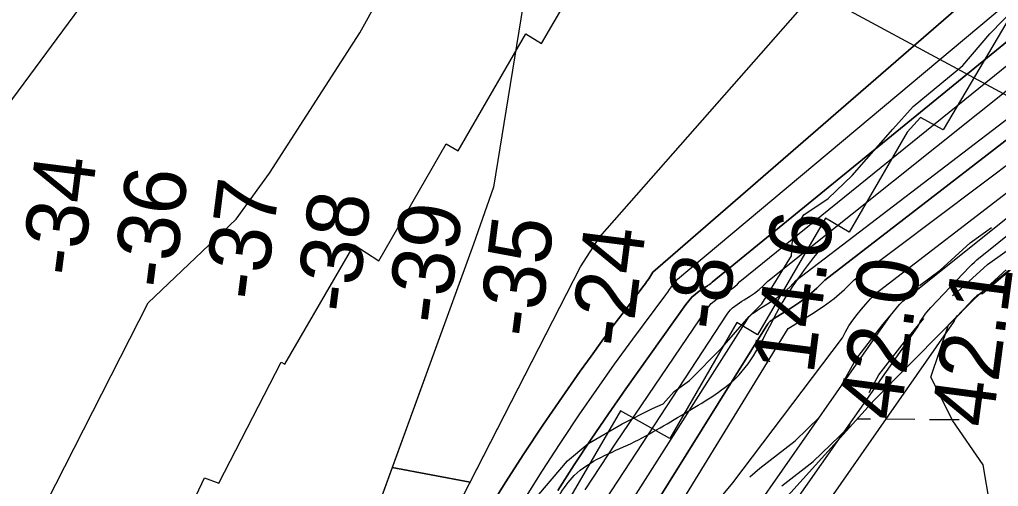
# Model space of a CAD drawing. Extents: x 3271442 to 3309282, y 752266 to 777610.
# Drawn here: x 3288016 to 3289076, y 761598 to 762104 of the extents above; entities that cross this region are included whole.
import ezdxf

# ---------------------------------------------------------------- set-up
doc = ezdxf.new("R2010")
doc.units = 0
for name, color, linetype in [('V-RIVR-EDGE', 7, 'Continuous'), ('V-RIVR-RANG', 7, 'Continuous'), ('V-ROAD-CNTR', 7, 'Continuous'), ('V-RRAP-FSHR', 7, 'Continuous'), ('V-RRAP-RVMT', 7, 'Continuous'), ('V-SITE-VEGE', 7, 'Continuous'), ('V-TOPO-DPTH', 7, 'Continuous'), ('V-TOPO-MAJR', 7, 'Continuous'), ('V-TOPO-MINR', 7, 'Continuous'), ('V-TOPO-WATR', 7, 'Continuous'), ('V-WETL-SWMP', 7, 'Continuous')]:
    doc.layers.add(name, color=color, linetype=linetype)

msp = doc.modelspace()

# ---------------------------------------------------------------- linework, layer by layer
at = {"layer": 'V-RIVR-EDGE'}
msp.add_lwpolyline([(3288561.9, 761569.6), (3288609.4, 761625.5), (3288631.6, 761644.2), (3288668.6, 761665.8), (3288701.7, 761682.2), (3288713, 761687.4), (3288725.2, 761700.9), (3288741.8, 761712.6), (3288776.7, 761748.1), (3288806.3, 761781.9), (3288820.2, 761795.8), (3288852.1, 761847.9), (3288853.4, 761864.9), (3288853.9, 761874), (3288865.7, 761892.2), (3288891.8, 761910), (3288917.9, 761934.7), (3288962, 761985), (3288984.2, 762009.7), (3289037.8, 762053.9), (3289067, 762088.2), (3289096.6, 762118.1)], dxfattribs=at)
at = {"layer": 'V-RIVR-RANG'}
msp.add_line((3289422.7, 761839.3), (3288525.2, 762323.9), dxfattribs=at)
at = {"layer": 'V-ROAD-CNTR'}
for points in [[(3288991.1, 761815.7), (3289013.3, 761832.3), (3289045.7, 761861.9), (3289068.9, 761878.3)], [(3289026.7, 761804.8), (3289032.4, 761809.1), (3289064.6, 761838.5), (3289104.8, 761867)], [(3288905.5, 761706.1), (3288921.8, 761735.3), (3288951.2, 761773.3), (3288963.1, 761787.5)], [(3288936.3, 761699.6), (3288946.9, 761718.7), (3288974.6, 761754.5), (3288995.7, 761779.8)], [(3288807, 761608.5), (3288817.8, 761617.6), (3288856, 761647.5), (3288882.8, 761673.5)], [(3288841.9, 761598.4), (3288875.7, 761624.8), (3288913.5, 761661.4), (3288915.9, 761665.3)]]:
    msp.add_lwpolyline(points, dxfattribs=at)
at = {"layer": 'V-RRAP-FSHR'}
msp.add_spline([(3288024.6, 760324), (3288039.3, 760373.1), (3288065.4, 760447.4), (3288088.5, 760530), (3288126.8, 760603.6), (3288137.9, 760646.8), (3288151, 760667.9), (3288170.6, 760680.2), (3288214.9, 760704), (3288256.5, 760693.3), (3288288, 760697.9), (3288339, 760715), (3288380, 760710.8), (3288399.4, 760726.3), (3288427.1, 760792.6), (3288462, 760862.2), (3288467.4, 760912.7), (3288487.8, 760995.5), (3288477.6, 761071), (3288451.3, 761142.3), (3288448.8, 761210.4), (3288443.2, 761290.4), (3288453.5, 761341), (3288469, 761381.1), (3288509, 761459.8), (3288586.4, 761563.5), (3288616.8, 761609.7), (3288678.4, 761644.6), (3288740.1, 761679.4), (3288795.5, 761719), (3288838.6, 761790.4), (3288890.2, 761863.5)], degree=3, dxfattribs=at)
at = {"layer": 'V-RRAP-RVMT'}
for points in [[(3288047.9, 761168.8), (3288047.6, 761183.6), (3288050, 761184.2), (3288052.9, 761205), (3288029.6, 761220.6), (3288061.8, 761268.1), (3288071.1, 761334.6), (3288077.4, 761334.7), (3288114, 761483.6), (3288153.2, 761474.1), (3288216.1, 761607.4), (3288231.7, 761601.6), (3288299, 761732.4), (3288303.1, 761730.4), (3288378.1, 761859.6), (3288404.9, 761842.3), (3288478, 761969), (3288490.9, 761961.4), (3288564.4, 762088.4), (3288581.3, 762077.7), (3288654.8, 762204)], [(3289090.3, 762108.9), (3289016.5, 761984.2), (3288991.9, 761997.7), (3288977.5, 761981.7), (3288914.6, 761873.4), (3288889, 761888.6), (3288815.3, 761762.2), (3288793, 761775.5), (3288720.4, 761650), (3288666.7, 761679.7), (3288593.8, 761554.4), (3288571.6, 761568.1), (3288510.1, 761451), (3288498.7, 761456.4), (3288469.1, 761394.2), (3288473.9, 761394), (3288445.6, 761283), (3288456.3, 761281.9), (3288446.5, 761214.5), (3288447, 761190.5), (3288462.2, 761191.4), (3288462.5, 761177.3)]]:
    msp.add_lwpolyline(points, dxfattribs=at)
at = {"layer": 'V-SITE-VEGE'}
msp.add_lwpolyline([(3289117, 761109.9), (3289055.4, 761114.6), (3289027, 761185.7), (3289027, 761200.1), (3289027, 761365.7), (3289017.5, 761379.9), (3289012.8, 761436.8), (3289017.5, 761469.9), (3289074.3, 761522), (3289074.3, 761536.2), (3289060.1, 761621.5), (3289027, 761668.9), (3289003.3, 761716.3), (3289022.3, 761773.1), (3289045.9, 761796.8), (3289107.5, 761853.6)], dxfattribs=at)
at = {"layer": 'V-TOPO-DPTH'}
for p, q in [((3289452.3, 762256.7), (3288888.2, 761821.3)), ((3288888.2, 761821.3), (3288879.7, 761812.8)), ((3288879.7, 761812.8), (3288870.8, 761804.8)), ((3288861.3, 761797.6), (3288851.4, 761790.9)), ((3288870.8, 761804.8), (3288861.3, 761797.6)), ((3288851.4, 761790.9), (3288832.6, 761779.4)), ((3288827.8, 761775.7), (3288827.1, 761774.9)), ((3288828.5, 761776.4), (3288827.8, 761775.7)), ((3288829.2, 761777), (3288828.5, 761776.4)), ((3288830.1, 761777.6), (3288829.2, 761777)), ((3288830.9, 761778.2), (3288830.1, 761777.6)), ((3288831.7, 761778.8), (3288830.9, 761778.2)), ((3288832.6, 761779.4), (3288831.7, 761778.8)), ((3288826.5, 761774.1), (3288629.6, 761458.5)), ((3288827.1, 761774.9), (3288826.5, 761774.1))]:
    msp.add_line(p, q, dxfattribs=at)
for points in [[(3288503.8, 761602.5), (3288623.5, 761835.8), (3288633.9, 761852), (3288644.3, 761868.2), (3289076.3, 762359.1), (3289585.9, 762757.5), (3289883.5, 763118.2)], [(3288320.8, 762441.7), (3287923.6, 761904.9)], [(3288320.8, 762441.7), (3287923.6, 761904.9)], [(3287738.3, 760513), (3288157.4, 760980.6), (3288277.3, 761160.7), (3288623.5, 761835.8), (3288633.9, 761852), (3288644.3, 761868.2), (3289076.3, 762359.1)], [(3289231.7, 762289.3), (3288702, 761830.1), (3288700.8, 761828.3), (3288699.7, 761826.5), (3288698.6, 761824.7), (3288697.4, 761823), (3288696.3, 761821.2), (3288695.1, 761819.5), (3288693.8, 761817.8), (3288692.6, 761816.1), (3288670.7, 761787.6), (3288658.6, 761771.5), (3288646.7, 761755.4), (3288634.9, 761739.1), (3288623.3, 761722.8), (3288603.6, 761694.8), (3288582.6, 761664.2), (3288562, 761633.3), (3288542, 761602), (3288522.5, 761570.3)], [(3289231.7, 762289.3), (3288702, 761830.1), (3288700.8, 761828.3), (3288699.7, 761826.5), (3288698.6, 761824.7), (3288697.4, 761823), (3288696.3, 761821.2), (3288695.1, 761819.5), (3288693.8, 761817.8), (3288692.6, 761816.1), (3288670.7, 761787.6), (3288658.6, 761771.5), (3288646.7, 761755.4), (3288634.9, 761739.1), (3288623.3, 761722.8), (3288603.6, 761694.8), (3288582.6, 761664.2), (3288562, 761633.3), (3288542, 761602), (3288522.5, 761570.3)], [(3288651.1, 761583.8), (3288782.4, 761784.4), (3288784.2, 761786.9), (3288786.2, 761789.2), (3288788.4, 761791.3), (3288790.8, 761793.3), (3288793.3, 761795.1), (3288795.8, 761796.8), (3288798.4, 761798.5), (3288801, 761800.2), (3288806.8, 761803.8), (3288812.1, 761807.4), (3288817.2, 761811.4), (3288821.9, 761815.7), (3288826.4, 761820.4), (3289419.8, 762294)], [(3288651.1, 761583.8), (3288782.4, 761784.4), (3288784.2, 761786.9), (3288786.2, 761789.2), (3288788.4, 761791.3), (3288790.8, 761793.3), (3288793.3, 761795.1), (3288795.8, 761796.8), (3288798.4, 761798.5), (3288801, 761800.2), (3288806.8, 761803.8), (3288812.1, 761807.4), (3288817.2, 761811.4), (3288821.9, 761815.7), (3288826.4, 761820.4), (3289419.8, 762294)], [(3288598.8, 761593.6), (3288616.7, 761621.5), (3288635, 761649.2), (3288653.7, 761676.6), (3288672.7, 761703.8), (3288737.5, 761794.9), (3288740.8, 761799), (3288744.3, 761802.8), (3288748.2, 761806.2), (3288752.3, 761809.4), (3288759.3, 761814.1), (3288760.2, 761814.7), (3288761.1, 761815.3), (3288762, 761815.9), (3288762.9, 761816.5), (3288763.8, 761817.1), (3288764.6, 761817.7), (3288765.4, 761818.4), (3288766.2, 761819.2), (3289335.6, 762283.8)], [(3289335.6, 762283.8), (3288766.2, 761819.2), (3288765.4, 761818.4), (3288764.6, 761817.7), (3288763.8, 761817.1), (3288762.9, 761816.5), (3288762, 761815.9), (3288761.1, 761815.3), (3288760.2, 761814.7), (3288759.3, 761814.1), (3288752.3, 761809.4), (3288748.2, 761806.2), (3288744.3, 761802.8), (3288740.8, 761799), (3288737.5, 761794.9), (3288672.7, 761703.8), (3288653.7, 761676.6), (3288635, 761649.2), (3288616.7, 761621.5), (3288598.8, 761593.6)], [(3287924.8, 761194.9), (3288044.8, 761580.5), (3288155, 761797), (3288250.5, 761887.3), (3288286.3, 761937.2), (3288384.4, 762089.4), (3288463.3, 762232.2), (3288501.5, 762258.3), (3288522.9, 762258.2), (3288549.1, 762248.6), (3288563.3, 762217.6), (3288568, 762160.5), (3288529.3, 761922.3), (3288507.7, 761860.5), (3288419.5, 761618.5), (3288503.8, 761602.5)], [(3288549.1, 762248.6), (3288563.3, 762217.6), (3288568, 762160.5), (3288529.3, 761922.3), (3288507.7, 761860.5), (3288251, 761156), (3288215.2, 761127.5), (3288165.2, 761115.7), (3288112.8, 761113.5), (3288048.5, 761116), (3287998.5, 761125.7), (3287955.6, 761132.9), (3287934.2, 761152), (3287924.8, 761194.9), (3288044.8, 761580.5), (3288155, 761797), (3288250.5, 761887.3), (3288286.3, 761937.2), (3288384.4, 762089.4), (3288463.3, 762232.2), (3288501.5, 762258.3), (3288522.9, 762258.2), (3288549.1, 762248.6)], [(3288501.3, 761597.5), (3288503.8, 761602.5), (3288419.5, 761618.5), (3288416.6, 761610.4), (3288251, 761156), (3288215.2, 761127.5), (3288165.2, 761115.7), (3288112.8, 761113.5), (3288048.5, 761116), (3287998.5, 761125.7)]]:
    msp.add_lwpolyline(points, dxfattribs=at)
at = {"layer": 'V-TOPO-MAJR'}
for p, q in [((3288972.9, 761798.8), (3289527.9, 762241.9)), ((3288969.4, 761795), (3288972.9, 761798.8)), ((3288959.4, 761783), (3288962.7, 761787.1)), ((3288962.7, 761787.1), (3288966, 761791.1)), ((3288966, 761791.1), (3288969.4, 761795)), ((3288699, 761410.1), (3288959.4, 761783))]:
    msp.add_line(p, q, dxfattribs=at)
at = {"layer": 'V-TOPO-MINR'}
for p, q in [((3289059.1, 761807.1), (3289603.7, 762270.1)), ((3288888.2, 761821.3), (3289452.3, 762256.7)), ((3289053.2, 761843.5), (3289565.9, 762256)), ((3288857, 761820.9), (3289416.7, 762249.1)), ((3288920.2, 761821.6), (3289462.9, 762231)), ((3288943, 761806.5), (3289489.6, 762228)), ((3289047.7, 761838.4), (3289050.4, 761841)), ((3289050.4, 761841), (3289053.2, 761843.5)), ((3289003.2, 761791.6), (3289045.1, 761835.7)), ((3289045.1, 761835.7), (3289047.7, 761838.4)), ((3288850.6, 761814.3), (3288857, 761820.9)), ((3288879.7, 761812.8), (3288888.2, 761821.3)), ((3288909.5, 761811.2), (3288920.2, 761821.6)), ((3288836.6, 761802.6), (3288843.8, 761808.1)), ((3288843.8, 761808.1), (3288850.6, 761814.3)), ((3288870.8, 761804.8), (3288879.7, 761812.8)), ((3288898.4, 761801.5), (3288909.5, 761811.2)), ((3288816.8, 761789.8), (3288829, 761797.4)), ((3288829, 761797.4), (3288836.6, 761802.6)), ((3288851.4, 761790.9), (3288861.3, 761797.6)), ((3288861.3, 761797.6), (3288870.8, 761804.8)), ((3288886.5, 761792.7), (3288898.4, 761801.5)), ((3288932.9, 761795.4), (3288937.9, 761801)), ((3288937.9, 761801), (3288943, 761806.5)), ((3289033.5, 761784.3), (3289049.2, 761800.9)), ((3289049.2, 761800.9), (3289050.2, 761801.9)), ((3289050.2, 761801.9), (3289051.2, 761802.9)), ((3289051.2, 761802.9), (3289052.2, 761803.8)), ((3289052.2, 761803.8), (3289053.3, 761804.8)), ((3289053.3, 761804.8), (3289053.5, 761805)), ((3289053.5, 761805), (3289054.5, 761805.7)), ((3289054.5, 761805.7), (3289055.6, 761806.3)), ((3289055.6, 761806.3), (3289056.7, 761806.7)), ((3289056.7, 761806.7), (3289057.9, 761807)), ((3289057.9, 761807), (3289059.1, 761807.1)), ((3288810, 761785.1), (3288811.7, 761786.4)), ((3288811.7, 761786.4), (3288813.3, 761787.5)), ((3288813.3, 761787.5), (3288815, 761788.7)), ((3288815, 761788.7), (3288816.8, 761789.8)), ((3288832.6, 761779.4), (3288851.4, 761790.9)), ((3288874, 761784.4), (3288886.5, 761792.7)), ((3288923.2, 761784.1), (3288928, 761789.8)), ((3288928, 761789.8), (3288932.9, 761795.4)), ((3288997, 761784.4), (3288999, 761786.8)), ((3288999, 761786.8), (3289001, 761789.2)), ((3289001, 761789.2), (3289003.2, 761791.6)), ((3288589.8, 761148.3), (3289028.4, 761776.6)), ((3288640.3, 761521.6), (3288804.5, 761779.2)), ((3288804.5, 761779.2), (3288805.7, 761780.9)), ((3288805.7, 761780.9), (3288807, 761782.4)), ((3288807, 761782.4), (3288808.5, 761783.8)), ((3288808.5, 761783.8), (3288810, 761785.1)), ((3288827.1, 761774.9), (3288827.8, 761775.7)), ((3288827.8, 761775.7), (3288828.5, 761776.4)), ((3288828.5, 761776.4), (3288829.2, 761777)), ((3288829.2, 761777), (3288830.1, 761777.6)), ((3288830.1, 761777.6), (3288830.9, 761778.2)), ((3288830.9, 761778.2), (3288831.7, 761778.8)), ((3288831.7, 761778.8), (3288832.6, 761779.4)), ((3288848.5, 761768.9), (3288874, 761784.4)), ((3288914.5, 761772), (3288918.6, 761778.1)), ((3288918.6, 761778.1), (3288923.2, 761784.1)), ((3288990.5, 761773.7), (3288991.8, 761776.5)), ((3288991.8, 761776.5), (3288993.3, 761779.2)), ((3288993.3, 761779.2), (3288995.1, 761781.8)), ((3288995.1, 761781.8), (3288997, 761784.4)), ((3289028.4, 761776.6), (3289028.8, 761777.7)), ((3289028.8, 761777.7), (3289029.3, 761778.7)), ((3289029.3, 761778.7), (3289029.8, 761779.7)), ((3289029.8, 761779.7), (3289030.5, 761780.7)), ((3289030.5, 761780.7), (3289031.2, 761781.7)), ((3289031.2, 761781.7), (3289031.9, 761782.6)), ((3289031.9, 761782.6), (3289032.7, 761783.5)), ((3289032.7, 761783.5), (3289033.5, 761784.3)), ((3288609, 761230.8), (3288989.3, 761770.7)), ((3288618.8, 761394.8), (3288848.5, 761768.9)), ((3288629.6, 761458.5), (3288826.5, 761774.1)), ((3288826.5, 761774.1), (3288827.1, 761774.9)), ((3288907.4, 761758.9), (3288910.8, 761765.5)), ((3288910.8, 761765.5), (3288914.5, 761772)), ((3288989.3, 761770.7), (3288990.5, 761773.7)), ((3288788.7, 761601.9), (3288907.4, 761758.9)), ((3288778.2, 761589.3), (3288788.7, 761601.9))]:
    msp.add_line(p, q, dxfattribs=at)
for points in [[(3288320.8, 762441.7), (3287923.6, 761904.9)], [(3287738.3, 760513), (3288157.4, 760980.6), (3288277.3, 761160.7), (3288623.5, 761835.8), (3288633.9, 761852), (3288644.3, 761868.2), (3289076.3, 762359.1)], [(3288628.5, 761594.3), (3288645.1, 761619.6), (3288661.9, 761644.8), (3288760.1, 761789.6), (3288762.6, 761792.9), (3288765.3, 761796), (3288768.3, 761798.8), (3288771.6, 761801.3), (3288772.2, 761801.8), (3288775.3, 761803.9), (3288778.4, 761806.1), (3288781.6, 761808.1), (3288784.8, 761810.1), (3288787.9, 761812.3), (3288790.8, 761814.6), (3288793.5, 761817.1), (3288796.1, 761819.9), (3289388, 762298.8)], [(3288522.5, 761570.3), (3288542, 761602), (3288562, 761633.3), (3288582.6, 761664.2), (3288603.6, 761694.8), (3288623.3, 761722.8), (3288634.9, 761739.1), (3288646.7, 761755.4), (3288658.6, 761771.5), (3288670.7, 761787.6), (3288692.6, 761816.1), (3288693.8, 761817.8), (3288695.1, 761819.5), (3288696.3, 761821.2), (3288697.4, 761823), (3288698.6, 761824.7), (3288699.7, 761826.5), (3288700.8, 761828.3), (3288702, 761830.1), (3289231.7, 762289.3)], [(3288598.8, 761593.6), (3288616.7, 761621.5), (3288635, 761649.2), (3288653.7, 761676.6), (3288672.7, 761703.8), (3288737.5, 761794.9), (3288740.8, 761799), (3288744.3, 761802.8), (3288748.2, 761806.2), (3288752.3, 761809.4), (3288759.3, 761814.1), (3288760.2, 761814.7), (3288761.1, 761815.3), (3288762, 761815.9), (3288762.9, 761816.5), (3288763.8, 761817.1), (3288764.6, 761817.7), (3288765.4, 761818.4), (3288766.2, 761819.2), (3289335.6, 762283.8)], [(3288033, 760667), (3288311.4, 761122.9), (3288527.5, 761523.3), (3288545.2, 761554), (3288563.3, 761584.5), (3288582, 761614.6), (3288601.3, 761644.4), (3288603.5, 761647.7), (3288622.1, 761675.5), (3288641.1, 761703.1), (3288660.5, 761730.3), (3288680.3, 761757.4), (3288715.9, 761805.6), (3288718, 761808.4), (3288720.1, 761811.2), (3288722.2, 761814), (3288724.4, 761816.9), (3288726.5, 761819.7), (3288728.6, 761822.5), (3289235.3, 762246.9)]]:
    msp.add_lwpolyline(points, dxfattribs=at)
msp.add_lwpolyline([(3287924.8, 761194.9), (3288044.8, 761580.5), (3288155, 761797), (3288250.5, 761887.3), (3288286.3, 761937.2), (3288384.4, 762089.4), (3288463.3, 762232.2), (3288501.5, 762258.3), (3288522.9, 762258.2), (3288549.1, 762248.6), (3288563.3, 762217.6), (3288568, 762160.5), (3288529.3, 761922.3), (3288507.7, 761860.5), (3288251, 761156), (3288215.2, 761127.5), (3288165.2, 761115.7), (3288112.8, 761113.5), (3288048.5, 761116), (3287998.5, 761125.7), (3287955.6, 761132.9), (3287934.2, 761152)], close=True, dxfattribs=at)
at = {"layer": 'V-TOPO-WATR'}
msp.add_lwpolyline([(3288651.1, 761583.8), (3288782.4, 761784.4), (3288784.2, 761786.9), (3288786.2, 761789.2), (3288788.4, 761791.3), (3288790.8, 761793.3), (3288793.3, 761795.1), (3288795.8, 761796.8), (3288798.4, 761798.5), (3288801, 761800.2), (3288806.8, 761803.8), (3288812.1, 761807.4), (3288817.2, 761811.4), (3288821.9, 761815.7), (3288826.4, 761820.4), (3289419.8, 762294)], dxfattribs=at)
at = {"layer": 'V-WETL-SWMP'}
for p, q in [((3289055.2, 761805.8), (3289124.6, 761862.3)), ((3288941.8, 761691.5), (3289055.2, 761805.8)), ((3288838, 761576.5), (3288941.8, 761691.5)), ((3288923.6, 761671.3), (3288937.8, 761671.1)), ((3288953.8, 761671), (3288985.8, 761670.7)), ((3289001.8, 761670.6), (3289033.8, 761670.3))]:
    msp.add_line(p, q, dxfattribs=at)

# ---------------------------------------------------------------- texts
at = {"layer": 'V-RIVR-RANG'}
for s, rotation, p in [('-34', 82.7374, (3288082.9, 761823.6)), ('-36', 82.7374, (3288182.1, 761810.4)), ('-37', 82.7374, (3288281.2, 761797.5)), ('-38', 82.7374, (3288380.3, 761784.1)), ('-39', 82.7374, (3288479.6, 761772)), ('14.6', 82.7374, (3288876, 761718.1)), ('-35', 82.7374, (3288578.5, 761757.3)), ('-24', 82.7374, (3288678, 761746.8)), ('-8', 82.7374, (3288781.1, 761765)), ('42.0', 82.4583, (3288969.8, 761668)), ('42.1', 82.4583, (3289069.6, 761660.3))]:
    msp.add_text(s, height=67, rotation=rotation, dxfattribs=at).set_placement(p)

doc.saveas('drawing.dxf')
